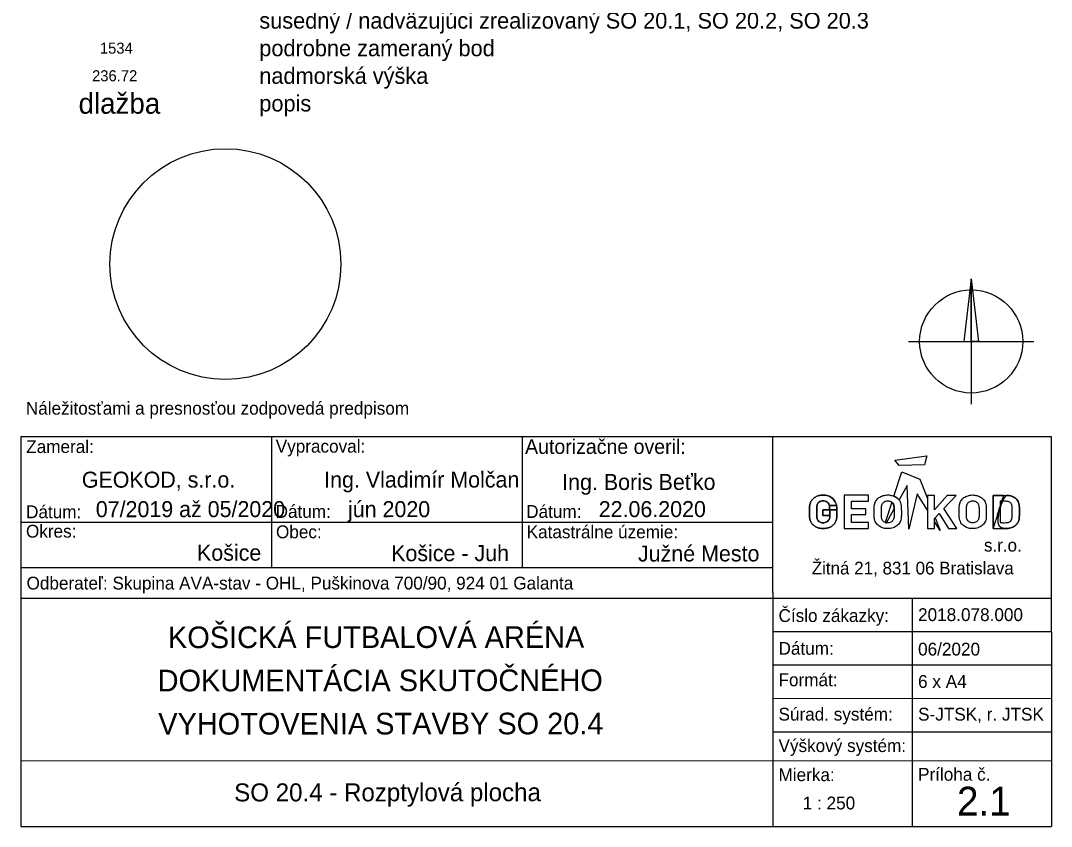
# Model space of a CAD drawing. Extents: x -264205 to -263659, y -1242401 to -1241986.
# Drawn here: x -263902.77 to -263860.8, y -1242216.83 to -1242184 of the extents above; entities that cross this region are included whole.
import ezdxf

# ---------------------------------------------------------------- set-up
doc = ezdxf.new("R2010")
doc.units = 0
doc.layers.add('LEGENDA_2-1', color=7, linetype='Continuous')
doc.layers.add('ROZPISKA_2-1', color=7, linetype='Continuous')

msp = doc.modelspace()

# ---------------------------------------------------------------- linework, layer by layer
at = {"layer": 'ROZPISKA_2-1'}
for p, q in [((-263864.061, -1242194.521), (-263864.363, -1242197.071)), ((-263864.061, -1242194.521), (-263864.061, -1242199.621)), ((-263864.061, -1242194.521), (-263863.759, -1242197.071)), ((-263866.611, -1242197.071), (-263861.511, -1242197.071)), ((-263902.769, -1242200.946), (-263902.77, -1242216.828)), ((-263902.769, -1242200.946), (-263860.799, -1242200.946)), ((-263892.562, -1242200.945), (-263892.559, -1242206.28)), ((-263882.353, -1242200.948), (-263882.35, -1242206.278)), ((-263872.141, -1242207.298), (-263872.143, -1242200.945)), ((-263860.799, -1242200.946), (-263860.798, -1242216.828)), ((-263867.21, -1242203.372), (-263866.881, -1242202.375)), ((-263866.881, -1242202.375), (-263866.149, -1242202.685)), ((-263866.671, -1242202.941), (-263866.999, -1242203.529)), ((-263866.607, -1242204.719), (-263866.671, -1242202.941)), ((-263866.149, -1242202.685), (-263865.84, -1242203.471)), ((-263867.477, -1242203.324), (-263867.454, -1242203.323)), ((-263866.256, -1242203.278), (-263866.607, -1242204.719)), ((-263865.84, -1242203.948), (-263866.256, -1242203.278)), ((-263865.554, -1242203.341), (-263865.84, -1242203.341)), ((-263865.84, -1242203.471), (-263865.84, -1242203.948)), ((-263865.036, -1242203.341), (-263865.554, -1242203.928)), ((-263865.554, -1242203.928), (-263865.554, -1242203.341)), ((-263865.172, -1242203.881), (-263864.679, -1242203.341)), ((-263864.679, -1242203.341), (-263865.036, -1242203.341)), ((-263863.17, -1242204.685), (-263863.169, -1242203.345)), ((-263863.169, -1242203.345), (-263863.17, -1242204.685)), ((-263863.169, -1242203.345), (-263862.74, -1242203.345)), ((-263862.74, -1242203.345), (-263863.169, -1242203.345)), ((-263869.534, -1242203.757), (-263869.832, -1242203.757)), ((-263869.832, -1242203.757), (-263869.534, -1242203.757)), ((-263867.291, -1242203.618), (-263867.564, -1242204.446)), ((-263867.472, -1242203.564), (-263867.457, -1242203.563)), ((-263867.472, -1242203.564), (-263867.457, -1242203.563)), ((-263864.652, -1242204.685), (-263865.172, -1242203.881)), ((-263862.876, -1242203.578), (-263862.876, -1242204.452)), ((-263862.876, -1242203.578), (-263862.876, -1242204.452)), ((-263865.531, -1242204.259), (-263865.329, -1242204.771)), ((-263902.771, -1242204.431), (-263872.142, -1242204.432)), ((-263865.329, -1242204.771), (-263865.554, -1242204.409)), ((-263864.991, -1242204.685), (-263864.652, -1242204.685)), ((-263902.77, -1242206.278), (-263872.143, -1242206.277)), ((-263902.773, -1242207.528), (-263872.139, -1242207.524)), ((-263872.141, -1242207.298), (-263872.142, -1242211.384)), ((-263872.139, -1242207.524), (-263860.798, -1242207.525)), ((-263866.471, -1242207.526), (-263866.47, -1242211.611)), ((-263872.142, -1242208.887), (-263860.799, -1242208.889)), ((-263872.144, -1242210.248), (-263860.798, -1242210.247)), ((-263872.142, -1242211.384), (-263872.142, -1242216.826)), ((-263872.144, -1242211.609), (-263860.797, -1242211.611)), ((-263866.47, -1242211.611), (-263866.469, -1242216.827)), ((-263872.142, -1242212.971), (-263860.797, -1242212.97)), ((-263902.771, -1242214.15), (-263860.798, -1242214.149)), ((-263902.77, -1242216.828), (-263860.798, -1242216.828))]:
    msp.add_line(p, q, dxfattribs=at)
for points in [[(-263864.061, -1242194.521), (-263863.759, -1242197.071), (-263864.061, -1242197.071)], [(-263867.172, -1242201.912), (-263865.872, -1242201.725), (-263865.963, -1242202.096), (-263866.999, -1242202.13)], [(-263869.238, -1242203.335), (-263869.238, -1242204.685), (-263868.249, -1242204.685), (-263868.249, -1242204.447), (-263868.942, -1242204.447), (-263868.942, -1242204.124), (-263868.35, -1242204.124), (-263868.35, -1242203.889), (-263868.942, -1242203.889), (-263868.942, -1242203.574), (-263868.249, -1242203.574), (-263868.249, -1242203.335)]]:
    msp.add_lwpolyline(points, close=True, dxfattribs=at)
for points in [[(-263866.999, -1242203.529), (-263867.008, -1242203.516), (-263867.025, -1242203.497), (-263867.043, -1242203.48), (-263867.062, -1242203.463), (-263867.082, -1242203.447), (-263867.104, -1242203.431), (-263867.123, -1242203.419), (-263867.143, -1242203.406), (-263867.167, -1242203.392), (-263867.188, -1242203.381), (-263867.21, -1242203.372)], [(-263865.84, -1242203.341), (-263865.84, -1242204.685), (-263865.554, -1242204.685), (-263865.554, -1242204.283), (-263865.363, -1242204.082), (-263864.991, -1242204.685)], [(-263867.518, -1242204.458), (-263867.202, -1242203.892)], [(-263867.202, -1242203.892), (-263867.203, -1242203.863), (-263867.204, -1242203.826), (-263867.207, -1242203.792), (-263867.212, -1242203.759), (-263867.22, -1242203.729), (-263867.232, -1242203.696), (-263867.25, -1242203.664), (-263867.269, -1242203.639), (-263867.291, -1242203.618)], [(-263869.822, -1242204.155), (-263870.103, -1242204.155), (-263870.103, -1242203.932), (-263869.531, -1242203.932)], [(-263869.531, -1242203.932), (-263870.103, -1242203.932), (-263870.103, -1242204.155), (-263869.822, -1242204.155)], [(-263865.554, -1242204.409), (-263865.554, -1242204.283), (-263865.531, -1242204.259)], [(-263867.564, -1242204.446), (-263867.557, -1242204.449), (-263867.548, -1242204.452), (-263867.54, -1242204.453), (-263867.532, -1242204.456), (-263867.524, -1242204.457), (-263867.518, -1242204.458)]]:
    msp.add_lwpolyline(points, dxfattribs=at)
for centre, radius in [((-263894.432, -1242193.918), 4.702), ((-263864.061, -1242197.071), 2.1)]:
    msp.add_circle(centre, radius, dxfattribs=at)
for points in [[(-263869.531, -1242203.932), (-263869.529, -1242204.102), (-263869.534, -1242204.255), (-263869.564, -1242204.391), (-263869.63, -1242204.5), (-263869.73, -1242204.592), (-263869.835, -1242204.653), (-263869.975, -1242204.688), (-263870.102, -1242204.697), (-263870.233, -1242204.688), (-263870.364, -1242204.644), (-263870.478, -1242204.57), (-263870.565, -1242204.483), (-263870.622, -1242204.365), (-263870.648, -1242204.234), (-263870.653, -1242204.146), (-263870.653, -1242203.879), (-263870.644, -1242203.735), (-263870.605, -1242203.613), (-263870.539, -1242203.508), (-263870.408, -1242203.403), (-263870.268, -1242203.342), (-263870.106, -1242203.324), (-263869.936, -1242203.337), (-263869.757, -1242203.412), (-263869.617, -1242203.543), (-263869.534, -1242203.757), (-263869.531, -1242203.932), (-263869.534, -1242203.757)], [(-263869.534, -1242203.757), (-263869.617, -1242203.543), (-263869.757, -1242203.412), (-263869.936, -1242203.337), (-263870.106, -1242203.324), (-263870.268, -1242203.342), (-263870.408, -1242203.403), (-263870.539, -1242203.508), (-263870.605, -1242203.613), (-263870.644, -1242203.735), (-263870.653, -1242203.879), (-263870.653, -1242204.146), (-263870.648, -1242204.234), (-263870.622, -1242204.365), (-263870.565, -1242204.483), (-263870.478, -1242204.57), (-263870.364, -1242204.644), (-263870.233, -1242204.688), (-263870.102, -1242204.697), (-263869.975, -1242204.688), (-263869.835, -1242204.653), (-263869.73, -1242204.592), (-263869.63, -1242204.5), (-263869.564, -1242204.391), (-263869.534, -1242204.255), (-263869.529, -1242204.102), (-263869.531, -1242203.932), (-263869.534, -1242203.757), (-263869.531, -1242203.932)], [(-263867.454, -1242203.323), (-263867.447, -1242203.323), (-263867.406, -1242203.322), (-263867.331, -1242203.34), (-263867.23, -1242203.358), (-263867.133, -1242203.41), (-263867.047, -1242203.471), (-263866.975, -1242203.554), (-263866.934, -1242203.648), (-263866.908, -1242203.752), (-263866.909, -1242203.915), (-263866.904, -1242204.083), (-263866.908, -1242204.247), (-263866.923, -1242204.351), (-263866.962, -1242204.438), (-263867.011, -1242204.514), (-263867.079, -1242204.573), (-263867.152, -1242204.627), (-263867.243, -1242204.663), (-263867.342, -1242204.692), (-263867.448, -1242204.699), (-263867.549, -1242204.692), (-263867.639, -1242204.684), (-263867.715, -1242204.649), (-263867.788, -1242204.607), (-263867.858, -1242204.562), (-263867.92, -1242204.497), (-263867.971, -1242204.409), (-263868.006, -1242204.302), (-263868.021, -1242204.126), (-263868.006, -1242203.962), (-263868.015, -1242203.805), (-263868.001, -1242203.715), (-263867.981, -1242203.628), (-263867.938, -1242203.549), (-263867.881, -1242203.485), (-263867.82, -1242203.428), (-263867.743, -1242203.387), (-263867.656, -1242203.348), (-263867.564, -1242203.329), (-263867.503, -1242203.325), (-263867.477, -1242203.324)], [(-263863.993, -1242203.323), (-263864.092, -1242203.33), (-263864.198, -1242203.353), (-263864.286, -1242203.39), (-263864.358, -1242203.431), (-263864.42, -1242203.486), (-263864.473, -1242203.549), (-263864.517, -1242203.629), (-263864.54, -1242203.717), (-263864.551, -1242203.802), (-263864.551, -1242203.897), (-263864.554, -1242204.187), (-263864.542, -1242204.295), (-263864.503, -1242204.415), (-263864.453, -1242204.5), (-263864.4, -1242204.556), (-263864.324, -1242204.609), (-263864.254, -1242204.648), (-263864.181, -1242204.678), (-263864.091, -1242204.692), (-263863.994, -1242204.696), (-263863.879, -1242204.687), (-263863.777, -1242204.659), (-263863.697, -1242204.625), (-263863.616, -1242204.57), (-263863.554, -1242204.512), (-263863.505, -1242204.441), (-263863.466, -1242204.348), (-263863.45, -1242204.254), (-263863.446, -1242204.136), (-263863.448, -1242203.857), (-263863.452, -1242203.749), (-263863.475, -1242203.652), (-263863.522, -1242203.553), (-263863.584, -1242203.48), (-263863.681, -1242203.408), (-263863.768, -1242203.364), (-263863.872, -1242203.339), (-263863.973, -1242203.323), (-263863.993, -1242203.323), (-263863.993, -1242203.323), (-263863.993, -1242203.323)], [(-263862.74, -1242203.345), (-263862.6, -1242203.345), (-263862.513, -1242203.349), (-263862.449, -1242203.362), (-263862.366, -1242203.391), (-263862.286, -1242203.436), (-263862.206, -1242203.51), (-263862.147, -1242203.595), (-263862.119, -1242203.674), (-263862.1, -1242203.798), (-263862.099, -1242203.859), (-263862.099, -1242204.126), (-263862.102, -1242204.214), (-263862.108, -1242204.285), (-263862.121, -1242204.361), (-263862.159, -1242204.455), (-263862.226, -1242204.541), (-263862.325, -1242204.619), (-263862.406, -1242204.655), (-263862.487, -1242204.678), (-263862.557, -1242204.685), (-263862.581, -1242204.685), (-263863.17, -1242204.685), (-263862.74, -1242203.345), (-263863.17, -1242204.685)], [(-263863.17, -1242204.685), (-263862.581, -1242204.685), (-263862.557, -1242204.685), (-263862.487, -1242204.678), (-263862.406, -1242204.655), (-263862.325, -1242204.619), (-263862.226, -1242204.541), (-263862.159, -1242204.455), (-263862.121, -1242204.361), (-263862.108, -1242204.285), (-263862.102, -1242204.214), (-263862.099, -1242204.126), (-263862.099, -1242203.859), (-263862.1, -1242203.798), (-263862.119, -1242203.674), (-263862.147, -1242203.595), (-263862.206, -1242203.51), (-263862.286, -1242203.436), (-263862.366, -1242203.391), (-263862.449, -1242203.362), (-263862.513, -1242203.349), (-263862.6, -1242203.345), (-263862.74, -1242203.345), (-263863.17, -1242204.685), (-263862.74, -1242203.345)], [(-263869.829, -1242203.757), (-263869.858, -1242203.683), (-263869.923, -1242203.611), (-263870.013, -1242203.57), (-263870.103, -1242203.563), (-263870.192, -1242203.574), (-263870.264, -1242203.615), (-263870.317, -1242203.672), (-263870.343, -1242203.734), (-263870.345, -1242203.825), (-263870.352, -1242203.926), (-263870.354, -1242204.046), (-263870.352, -1242204.188), (-263870.341, -1242204.293), (-263870.302, -1242204.376), (-263870.245, -1242204.424), (-263870.177, -1242204.453), (-263870.105, -1242204.461), (-263870.02, -1242204.457), (-263869.93, -1242204.42), (-263869.867, -1242204.359), (-263869.829, -1242204.289), (-263869.821, -1242204.208), (-263869.822, -1242204.155), (-263869.829, -1242203.757), (-263869.822, -1242204.155)], [(-263869.822, -1242204.155), (-263869.821, -1242204.208), (-263869.829, -1242204.289), (-263869.867, -1242204.359), (-263869.93, -1242204.42), (-263870.02, -1242204.457), (-263870.105, -1242204.461), (-263870.177, -1242204.453), (-263870.245, -1242204.424), (-263870.302, -1242204.376), (-263870.341, -1242204.293), (-263870.352, -1242204.188), (-263870.354, -1242204.046), (-263870.352, -1242203.926), (-263870.345, -1242203.825), (-263870.343, -1242203.734), (-263870.317, -1242203.672), (-263870.264, -1242203.615), (-263870.192, -1242203.574), (-263870.103, -1242203.563), (-263870.013, -1242203.57), (-263869.923, -1242203.611), (-263869.858, -1242203.683), (-263869.829, -1242203.757), (-263869.822, -1242204.155), (-263869.829, -1242203.757)], [(-263867.457, -1242203.563), (-263867.444, -1242203.563), (-263867.413, -1242203.564), (-263867.36, -1242203.576), (-263867.3, -1242203.607), (-263867.247, -1242203.658), (-263867.214, -1242203.734), (-263867.2, -1242203.816), (-263867.203, -1242203.908), (-263867.2, -1242204.003), (-263867.203, -1242204.102), (-263867.199, -1242204.193), (-263867.212, -1242204.27), (-263867.23, -1242204.339), (-263867.273, -1242204.401), (-263867.337, -1242204.443), (-263867.406, -1242204.462), (-263867.462, -1242204.458), (-263867.513, -1242204.461), (-263867.567, -1242204.448), (-263867.621, -1242204.415), (-263867.671, -1242204.366), (-263867.707, -1242204.293), (-263867.718, -1242204.205), (-263867.714, -1242204.099), (-263867.717, -1242203.981), (-263867.714, -1242203.867), (-263867.711, -1242203.774), (-263867.696, -1242203.701), (-263867.656, -1242203.641), (-263867.601, -1242203.596), (-263867.536, -1242203.567), (-263867.491, -1242203.564), (-263867.472, -1242203.564)], [(-263867.457, -1242203.563), (-263867.444, -1242203.563), (-263867.413, -1242203.564), (-263867.36, -1242203.576), (-263867.3, -1242203.607), (-263867.247, -1242203.658), (-263867.214, -1242203.734), (-263867.2, -1242203.816), (-263867.203, -1242203.908), (-263867.2, -1242204.003), (-263867.203, -1242204.102), (-263867.199, -1242204.193), (-263867.212, -1242204.27), (-263867.23, -1242204.339), (-263867.273, -1242204.401), (-263867.337, -1242204.443), (-263867.406, -1242204.462), (-263867.462, -1242204.458), (-263867.513, -1242204.461), (-263867.567, -1242204.448), (-263867.621, -1242204.415), (-263867.671, -1242204.366), (-263867.707, -1242204.293), (-263867.718, -1242204.205), (-263867.714, -1242204.099), (-263867.717, -1242203.981), (-263867.714, -1242203.867), (-263867.711, -1242203.774), (-263867.696, -1242203.701), (-263867.656, -1242203.641), (-263867.601, -1242203.596), (-263867.536, -1242203.567), (-263867.491, -1242203.564), (-263867.472, -1242203.564)], [(-263863.996, -1242203.563), (-263864.069, -1242203.57), (-263864.14, -1242203.6), (-263864.195, -1242203.646), (-263864.23, -1242203.699), (-263864.248, -1242203.772), (-263864.253, -1242203.853), (-263864.255, -1242203.975), (-263864.255, -1242204.113), (-263864.255, -1242204.208), (-263864.241, -1242204.293), (-263864.205, -1242204.367), (-263864.156, -1242204.415), (-263864.106, -1242204.445), (-263864.048, -1242204.459), (-263864.002, -1242204.459), (-263863.956, -1242204.459), (-263863.882, -1242204.441), (-263863.811, -1242204.392), (-263863.774, -1242204.339), (-263863.753, -1242204.272), (-263863.741, -1242204.196), (-263863.741, -1242204.109), (-263863.741, -1242204), (-263863.741, -1242203.901), (-263863.742, -1242203.822), (-263863.76, -1242203.726), (-263863.79, -1242203.662), (-263863.843, -1242203.609), (-263863.905, -1242203.576), (-263863.958, -1242203.565), (-263863.996, -1242203.563), (-263863.996, -1242203.563), (-263863.996, -1242203.563)], [(-263862.876, -1242204.452), (-263862.79, -1242204.453), (-263862.701, -1242204.453), (-263862.607, -1242204.452), (-263862.59, -1242204.453), (-263862.556, -1242204.445), (-263862.502, -1242204.418), (-263862.434, -1242204.371), (-263862.401, -1242204.287), (-263862.391, -1242204.197), (-263862.392, -1242204.071), (-263862.391, -1242203.927), (-263862.392, -1242203.81), (-263862.399, -1242203.731), (-263862.43, -1242203.676), (-263862.489, -1242203.62), (-263862.556, -1242203.59), (-263862.648, -1242203.577), (-263862.71, -1242203.577), (-263862.837, -1242203.578), (-263862.876, -1242203.578)], [(-263862.876, -1242204.452), (-263862.79, -1242204.453), (-263862.701, -1242204.453), (-263862.607, -1242204.452), (-263862.59, -1242204.453), (-263862.556, -1242204.445), (-263862.502, -1242204.418), (-263862.434, -1242204.371), (-263862.401, -1242204.287), (-263862.391, -1242204.197), (-263862.392, -1242204.071), (-263862.391, -1242203.927), (-263862.392, -1242203.81), (-263862.399, -1242203.731), (-263862.43, -1242203.676), (-263862.489, -1242203.62), (-263862.556, -1242203.59), (-263862.648, -1242203.577), (-263862.71, -1242203.577), (-263862.837, -1242203.578), (-263862.876, -1242203.578)]]:
    msp.add_open_spline(points, degree=3, dxfattribs=at)

# ---------------------------------------------------------------- texts
at = {"layer": 'LEGENDA_2-1'}
for s, height, p in [('susedný / nadväzujúci zrealizovaný SO 20.1, SO 20.2, SO 20.3', 0.66129, (-263893.052, -1242184.324)), ('1534', 0.45, (-263899.545, -1242185.344)), ('podrobne zameraný bod', 0.66129, (-263893.052, -1242185.449)), ('236.72', 0.45, (-263899.863, -1242186.469)), ('nadmorská výška', 0.66129, (-263893.052, -1242186.574)), ('dlažba', 0.8438, (-263900.413, -1242187.791)), ('popis', 0.6613, (-263893.052, -1242187.699))]:
    msp.add_text(s, height=height, dxfattribs=at).set_placement(p)
at = {"layer": 'ROZPISKA_2-1'}
for s, height, rotation, p in [('Náležitosťami a presnosťou zodpovedá predpisom', 0.5217, 0.0016, (-263902.56, -1242200.052)), ('Zameral:', 0.5217, 0.0016, (-263902.544, -1242201.614)), ('Vypracoval:', 0.5217, 0.0016, (-263892.383, -1242201.599)), ('Autorizačne overil:', 0.59461, 0.0016, (-263882.229, -1242201.65)), ('GEOKOD, s.r.o.', 0.65196, 0.0456, (-263900.28, -1242203.028)), ('Ing. Vladimír Molčan', 0.65209, 0.0456, (-263890.411, -1242203.026)), ('Ing. Boris Beťko', 0.65241, 0.0456, (-263880.719, -1242203.123)), ('Dátum:', 0.5217, 0.0016, (-263902.551, -1242204.271)), ('07/2019 až 05/2020', 0.65196, 0.0456, (-263899.711, -1242204.23)), ('Dátum:', 0.5217, 0.0016, (-263892.388, -1242204.257)), ('jún 2020', 0.652, 0.0456, (-263889.44, -1242204.23)), ('Dátum:', 0.5217, 0.0016, (-263882.184, -1242204.258)), ('22.06.2020', 0.652, 0.0456, (-263879.23, -1242204.227)), ('Okres:', 0.5217, 0.0016, (-263902.554, -1242205.062)), ('Obec:', 0.5217, 0.0016, (-263892.373, -1242205.087)), ('Katastrálne územie:', 0.5217, 0.0016, (-263882.165, -1242205.089)), ('Košice', 0.6523, 0.0456, (-263895.589, -1242206.003)), ('Košice - Juh', 0.65241, 0.0456, (-263887.684, -1242206.023)), ('Južné Mesto', 0.65241, 0.0456, (-263877.632, -1242206.036)), ('s.r.o.', 0.5173, 0.0016, (-263863.542, -1242205.63)), ('Žitná 21, 831 06 Bratislava', 0.51728, 0.0016, (-263870.557, -1242206.562)), ('Odberateľ: Skupina AVA-stav - OHL, Puškinova 700/90, 924 01 Galanta', 0.52157, 0.0016, (-263902.531, -1242207.176)), ('Číslo zákazky:', 0.52157, 0.0016, (-263871.908, -1242208.499)), ('KOŠICKÁ FUTBALOVÁ ARÉNA', 0.88076, 0.0456, (-263896.77, -1242209.565)), ('Dátum:', 0.5217, 0.0016, (-263871.908, -1242209.834)), ('DOKUMENTÁCIA SKUTOČNÉHO', 0.88076, 0.0456, (-263897.191, -1242211.327)), ('Formát:', 0.5217, 0.0016, (-263871.908, -1242211.116)), ('VYHOTOVENIA STAVBY SO 20.4', 0.88076, 0.0456, (-263897.168, -1242213.089)), ('Súrad. systém:', 0.52157, 0.0016, (-263871.908, -1242212.516)), ('Výškový systém:', 0.52156, 0.0016, (-263871.908, -1242213.798)), ('Mierka:', 0.5217, 0.0016, (-263871.908, -1242214.983)), ('Príloha č.', 0.5216, 0.0016, (-263866.226, -1242214.966)), ('SO 20.4 - Rozptylová plocha', 0.73378, 0.0456, (-263894.075, -1242215.811))]:
    msp.add_text(s, height=height, rotation=rotation, dxfattribs=at).set_placement(p)
for s, height, p in [('2018.078.000', 0.52245, (-263866.226, -1242208.462)), ('06/2020', 0.5224, (-263866.226, -1242209.867)), ('6 x A4', 0.5224, (-263866.226, -1242211.185)), ('S-JTSK, r. JTSK', 0.52245, (-263866.226, -1242212.519)), ('2.1', 1.1755, (-263864.64, -1242216.386)), ('1 : 250', 0.5224, (-263870.923, -1242216.136))]:
    msp.add_text(s, height=height, dxfattribs=at).set_placement(p)

doc.saveas('drawing.dxf')
